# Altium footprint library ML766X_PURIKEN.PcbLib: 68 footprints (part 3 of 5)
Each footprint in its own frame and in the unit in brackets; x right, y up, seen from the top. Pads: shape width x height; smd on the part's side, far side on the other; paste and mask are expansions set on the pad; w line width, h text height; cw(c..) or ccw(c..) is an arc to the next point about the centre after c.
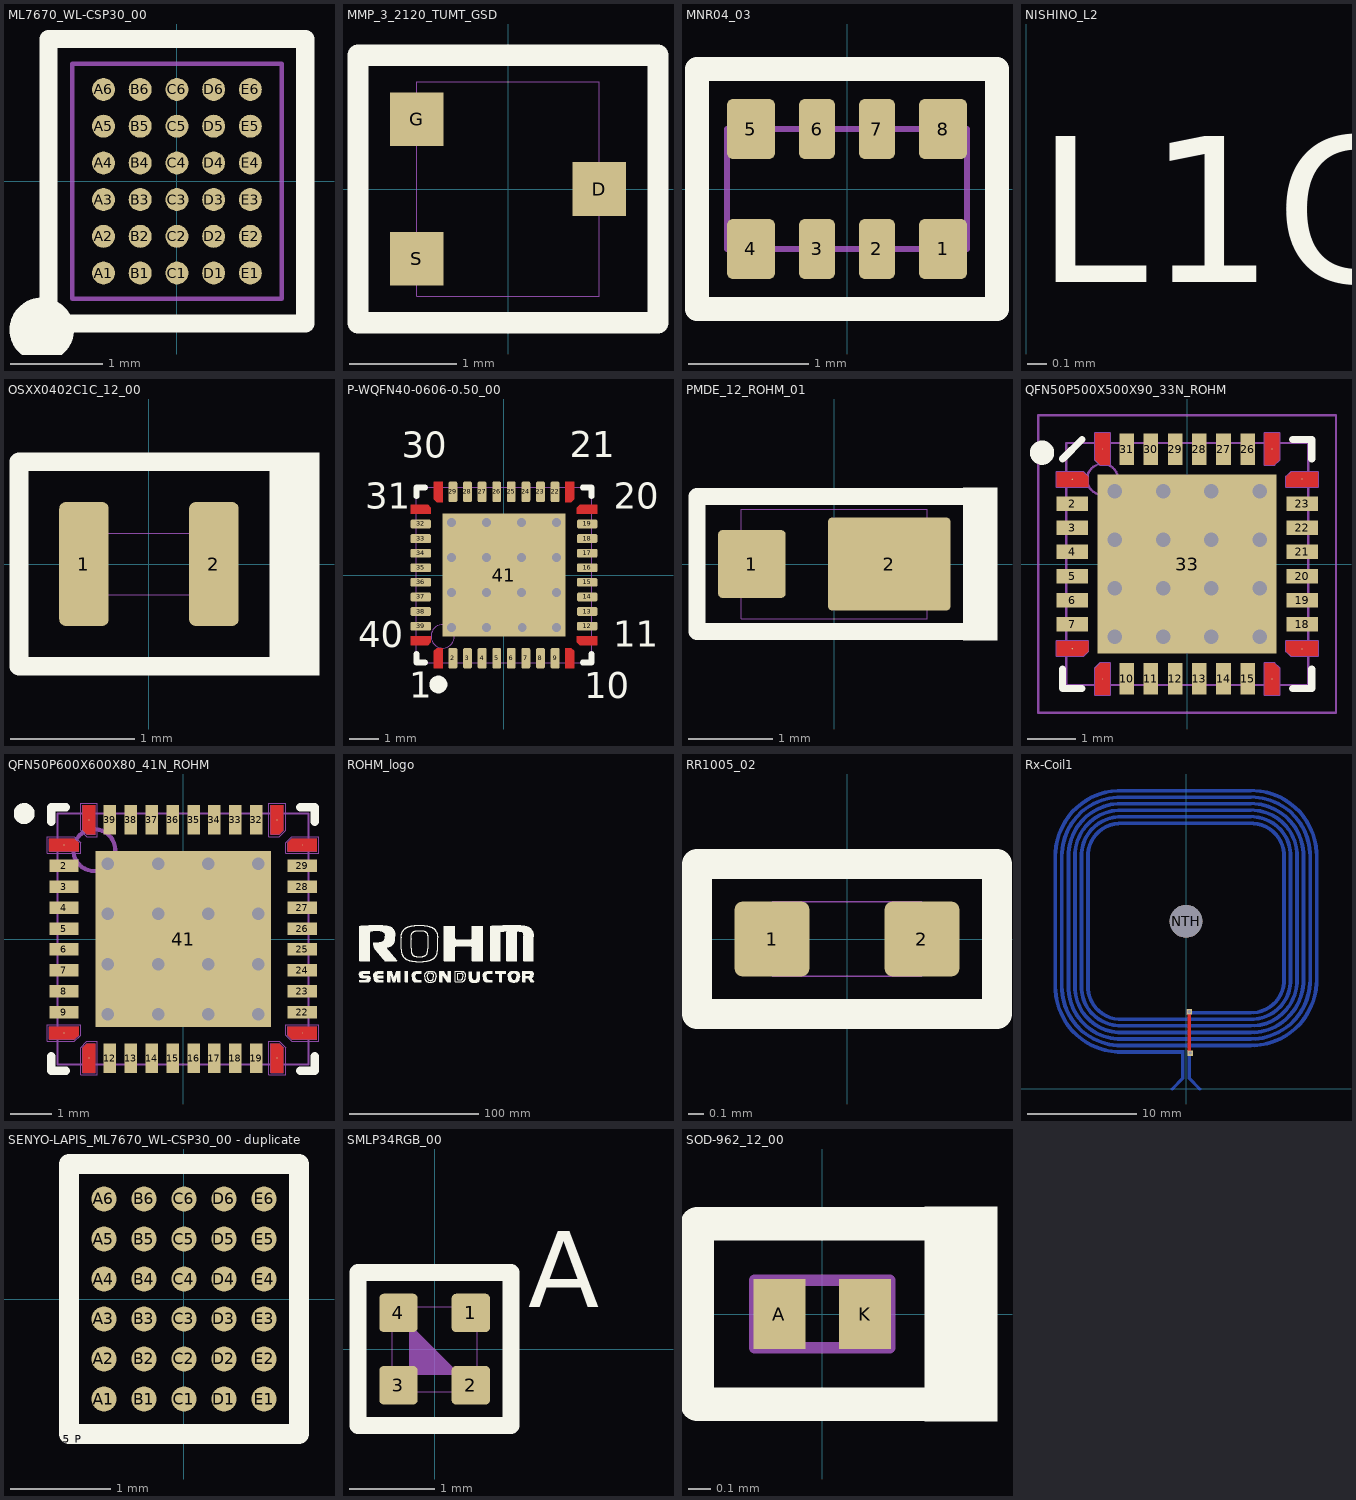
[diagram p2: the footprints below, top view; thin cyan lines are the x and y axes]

## ML7670_WL-CSP30_00 [mm]
height 0.48
pads (30):
  round 0.25 smd paste-2539.97 mask+0.013: A1(-0.8,-1) A2(-0.8,-0.6) A3(-0.8,-0.2) A4(-0.8,0.2) A5(-0.8,0.6) A6(-0.8,1) B1(-0.4,-1) B2(-0.4,-0.6) B3(-0.4,-0.2) B4(-0.4,0.2) B5(-0.4,0.6) B6(-0.4,1) C1(0,-1) C2(0,-0.6) C3(0,-0.2) C4(0,0.2) C5(0,0.6) C6(0,1) D1(0.4,-1) D2(0.4,-0.6) D3(0.4,-0.2) D4(0.4,0.2) D5(0.4,0.6) D6(0.4,1) E1(0.8,-1) E2(0.8,-0.6) E3(0.8,-0.2) E4(0.8,0.2) E5(0.8,0.6) E6(0.8,1)
Top Overlay:
  circle w0.5: c-1.473,-1.619 r0.1
  lines w0.2: -1.4,-1.55 0.2,-1.55 1.4,-1.55 1.4,1.55 -1.4,1.55 -1.4,-1.55
Top Component Outline:
  lines w0.05: -1.14,-1.28 -1.14,1.28 1.14,1.28 1.14,-1.28 -1.14,-1.28
3D body: height 0.4, standoff 0, extent -1.14,-1.28 1.14,1.28
3D body: height 0.41, standoff 0.4, extent -0.993,-1.212 -0.593,-0.812

## MMP_3_2120_TUMT_GSD [mm] "default"
height 0.9
pads (3):
  rect 0.5x0.5 smd paste+0 mask+0.05: D(0.85,0) G(-0.85,0.65) S(-0.85,-0.65)
Top Overlay:
  lines w0.2: -1.4,-1.25 1.4,-1.25 1.4,1 1.4,1.25 -1.4,1.25 -1.4,0.3 -1.4,-1.25
Top Component Outline:
  lines w0.01: -1.05,-0.8 -0.65,-0.8 -0.65,-0.5 -1.05,-0.5 -1.05,-0.8 ; -1.05,0.5 -0.65,0.5 -0.65,0.8 -1.05,0.8 -1.05,0.5 ; -0.85,-1 0.85,-1 0.85,1 -0.85,1 -0.85,-1 ; 0.65,-0.15 0.65,0.15 1.05,0.15 1.05,-0.15 0.65,-0.15
3D body "sot-323t_TUMT3.STEP": height 0.85, standoff 0, extent -1.05,-1 1.05,1

## MNR04_03 [mm]
height 0.35
pads (8):
  rrect25% 0.4x0.5 smd paste-2539.97 mask+0.025: 1(0.8,-0.5) 4(-0.8,-0.5) 5(-0.8,0.5) 8(0.8,0.5)
  rrect33% 0.3x0.5 smd paste-2539.97 mask+0.025: 2(0.25,-0.5) 3(-0.25,-0.5) 6(-0.25,0.5) 7(0.25,0.5)
Top Overlay:
  lines w0.2: -1.25,-1 0,-1 1.25,-1 1.25,1 -1.25,1 -1.25,-1
Top Component Outline:
  lines w0.05: -1,-0.5 -1,0.5 1,0.5 1,-0.5 -1,-0.5
3D body "MNR04.step": height 0.35, standoff 0, extent -1,-0.5 1,0.5

## NISHINO_L2 [mm]
Top Layer:
  text "L1PT" at 0,-1.15 h1.52
Bottom Layer:
  text "L2PT" at 2.831,-1.2 h1.52
Top Overlay:
  text "L1CM" at 0.05,-4.417 h1.52
Bottom Overlay:
  text "L2CM" at 3.433,-4.367 h1.52
MASK:
  text "L1METAL" at 0.1,-6 h1.52
MASK_B:
  text "L2METAL" at 5.815,-6.05 h1.52
Top Solder:
  text "L1SR" at 0.05,-2.867 h1.52
Bottom Solder:
  text "L2SR" at 3.04,-2.867 h1.52

## OSXX0402C1C_12_00 [mm]
height 0.4
pads (2):
  rrect25% 0.4x1 smd: 1(-0.525,0) 2(0.525,0)
Top Overlay:
  region: 0.975,0.9 1.375,0.9 1.375,-0.9 0.975,-0.9
  lines w0.15: 1.3,-0.825 -1.05,-0.825 -1.05,0.825 1.3,0.825
Top Component Outline:
  lines w0.01: -0.5,-0.25 0.5,-0.25 0.5,0.25 -0.5,0.25 -0.5,-0.25
3D body: height 0.4, standoff 0, extent -0.5,-0.25 0.5,0.25

## P-WQFN40-0606-0.50_00 [mm]
height 0.8
pads (57):
  round 0.005 smd: 1(-2.25,-2.85) 10(2.25,-2.85) 11(2.85,-2.25) 20(2.85,2.25) 21(2.25,2.85) 30(-2.25,2.85) 31(-2.85,2.25) 40(-2.85,-2.25)
  rrect33% 0.3x0.7 smd paste-2539.97 mask+0.025: 2(-1.75,-2.85) 3(-1.25,-2.85) 4(-0.75,-2.85) 5(-0.25,-2.85) 6(0.25,-2.85) 7(0.75,-2.85) 8(1.25,-2.85) 9(1.75,-2.85) 22(1.75,2.85) 23(1.25,2.85) 24(0.75,2.85) 25(0.25,2.85) 26(-0.25,2.85) 27(-0.75,2.85) 28(-1.25,2.85) 29(-1.75,2.85)
  rrect33% 0.7x0.3 smd paste-2539.97 mask+0.025: 12(2.85,-1.75) 13(2.85,-1.25) 14(2.85,-0.75) 15(2.85,-0.25) 16(2.85,0.25) 17(2.85,0.75) 18(2.85,1.25) 19(2.85,1.75) 32(-2.85,1.75) 33(-2.85,1.25) 34(-2.85,0.75) 35(-2.85,0.25) 36(-2.85,-0.25) 37(-2.85,-0.75) 38(-2.85,-1.25) 39(-2.85,-1.75)
  rect 4.2x4.2 smd mask+0.051: 41(0,0)
  round 0.6 / inner round 1.524 / far side round 0.6 hole 0.3 mask-0.051: VIA0.3_0.6_0.6_00(-1.8,-1.8) VIA0.3_0.6_0.6_00(-1.8,-0.6) VIA0.3_0.6_0.6_00(-1.8,0.6) VIA0.3_0.6_0.6_00(-1.8,1.8) VIA0.3_0.6_0.6_00(-0.6,-1.8) VIA0.3_0.6_0.6_00(-0.6,-0.6) VIA0.3_0.6_0.6_00(-0.6,0.6) VIA0.3_0.6_0.6_00(-0.6,1.8) VIA0.3_0.6_0.6_00(0.6,-0.6) VIA0.3_0.6_0.6_00(0.6,0.6) VIA0.3_0.6_0.6_00(0.6,1.8) VIA0.3_0.6_0.6_00(0.625,-1.8) VIA0.3_0.6_0.6_00(1.8,-1.8) VIA0.3_0.6_0.6_00(1.8,-0.6) VIA0.3_0.6_0.6_00(1.8,0.6) VIA0.3_0.6_0.6_00(1.8,1.8)
Top Layer:
  region: -2.5,-2.1 -2.5,-2.3 -2.6,-2.4 -3.2,-2.4 -3.2,-2.1
  region: -2.5,2.3 -2.5,2.1 -3.2,2.1 -3.2,2.4 -2.6,2.4
  region: -2.1,2.5 -2.3,2.5 -2.4,2.6 -2.4,3.2 -2.1,3.2
  region: 2.3,2.5 2.1,2.5 2.1,3.2 2.4,3.2 2.4,2.6
  region: 2.5,2.1 2.5,2.3 2.6,2.4 3.2,2.4 3.2,2.1
  region: 2.5,-2.3 2.5,-2.1 3.2,-2.1 3.2,-2.4 2.6,-2.4
  region: 2.1,-2.5 2.3,-2.5 2.4,-2.6 2.4,-3.2 2.1,-3.2
  region: -2.3,-2.5 -2.1,-2.5 -2.1,-3.2 -2.4,-3.2 -2.4,-2.6
Top Overlay:
  region: -1.95,-3.75 -1.95,-3.69 -1.996,-3.58 -2.08,-3.496 -2.19,-3.45 -2.31,-3.45 -2.42,-3.496 -2.504,-3.58 -2.55,-3.69 -2.55,-3.81 -2.504,-3.92 -2.42,-4.004 -2.31,-4.05 -2.25,-4.05 -2.19,-4.05 -2.08,-4.004 -1.996,-3.92 -1.95,-3.81 -1.95,-3.69 -1.996,-3.58 -2.08,-3.496 -2.19,-3.45 -2.31,-3.45 -2.42,-3.496 -2.504,-3.58 -2.55,-3.69 -2.55,-3.75 -2.55,-3.81 -2.504,-3.92 -2.42,-4.004 -2.31,-4.05 -2.19,-4.05 -2.08,-4.004 -1.996,-3.92 -1.95,-3.81 -1.95,-3.69 -1.996,-3.58 -2.08,-3.496 -2.19,-3.45 -2.25,-3.45 -2.31,-3.45 -2.42,-3.496 -2.504,-3.58 -2.55,-3.69 -2.55,-3.81 -2.504,-3.92 -2.42,-4.004 -2.31,-4.05 -2.19,-4.05 -2.08,-4.004 -1.996,-3.92 -1.95,-3.81
  lines w0.2: -3,-2.7 -3,-3 -2.7,-3 ; -3,2.7 -3,3 -2.7,3 ; 2.7,-3 3,-3 3,-2.7 ; 2.7,3 3,3 3,2.7
  text "40" at -5,-2.767 h1.52
  text "1" at -3.25,-4.5 h1.52
  text "10" at 2.75,-4.517 h1.52
  text "11" at 3.75,-2.75 h1.52
  text "20" at 3.751,1.983 h1.52
  text "21" at 2.251,3.75 h1.52
  text "30" at -3.5,3.733 h1.52
  text "31" at -4.75,1.983 h1.52
MASK:
  dashed: -2.5,-2.1 -2.5,-2.3 -2.6,-2.4 -3.2,-2.4 -3.2,-2.1
  dashed: -2.5,2.3 -2.5,2.1 -3.2,2.1 -3.2,2.4 -2.6,2.4
  dashed: -2.1,2.5 -2.3,2.5 -2.4,2.6 -2.4,3.2 -2.1,3.2
  dashed: 2.3,2.5 2.1,2.5 2.1,3.2 2.4,3.2 2.4,2.6
  dashed: 2.5,2.1 2.5,2.3 2.6,2.4 3.2,2.4 3.2,2.1
  dashed: 2.5,-2.3 2.5,-2.1 3.2,-2.1 3.2,-2.4 2.6,-2.4
  dashed: 2.1,-2.5 2.3,-2.5 2.4,-2.6 2.4,-3.2 2.1,-3.2
  dashed: -2.3,-2.5 -2.1,-2.5 -2.1,-3.2 -2.4,-3.2 -2.4,-2.6
  region: -2.1,-2.1 -2.1,-0.15 -0.15,-0.15 -0.15,-2.1
  region: -2.1,0.15 -2.1,2.1 -0.15,2.1 -0.15,0.15
  region: 0.15,-2.1 0.15,-0.15 2.1,-0.15 2.1,-2.1
  region: 0.15,0.15 0.15,2.1 2.1,2.1 2.1,0.15
Top Solder:
  dashed: -3.25,-2.05 -2.45,-2.05 -2.45,-2.321 -2.579,-2.45 -3.25,-2.45
  dashed: -3.25,2.45 -2.579,2.45 -2.45,2.321 -2.45,2.05 -3.25,2.05
  dashed: -2.05,3.25 -2.05,2.45 -2.321,2.45 -2.45,2.579 -2.45,3.25
  dashed: 2.45,3.25 2.45,2.579 2.321,2.45 2.05,2.45 2.05,3.25
  dashed: 3.25,2.05 2.45,2.05 2.45,2.321 2.579,2.45 3.25,2.45
  dashed: 3.25,-2.45 2.579,-2.45 2.45,-2.321 2.45,-2.05 3.25,-2.05
  dashed: 2.05,-3.25 2.05,-2.45 2.321,-2.45 2.45,-2.579 2.45,-3.25
  dashed: -2.45,-3.25 -2.45,-2.579 -2.321,-2.45 -2.05,-2.45 -2.05,-3.25
Top Component Outline:
  circle w0.01: c-2.1,-2.1 r0.4
  lines w0.01: -3,-3 3,-3 3,3 -3,3 -3,-3
3D body: height 0.8, standoff 0, extent -3,-3 3,3

## PCBComponent_1 [mm]

## PMDE_12_ROHM_01 [mm]
height 0.95
pads (2):
  rrect12% 0.8x0.8 smd: 1(-0.975,0)
  rrect9% 1.45x1.1 smd: 2(0.65,0)
Top Overlay:
  region: 1.525,0.9 1.925,0.9 1.925,-0.9 1.525,-0.9
  lines w0.2: 1.625,-0.8 -1.625,-0.8 -1.625,0.8 1.625,0.8
Top Component Outline:
  lines w0.01: -1.1,-0.65 1.1,-0.65 1.1,0.65 -1.1,0.65 -1.1,-0.65
3D body: height 0.95, standoff 0, extent -1.1,-0.65 1.1,0.65

## QFN50P500X500X90_33N_ROHM [mm] "QFN, 32-Leads, Body 5.00x5.00mm, Pitch 0.50mm, Thermal Pad 3.90x3.90mm"
height 0.9
pads (33):
  round 0.025 smd mask+0.05: 1(-2.375,1.75) 8(-2.375,-1.75) 9(-1.75,-2.375) 16(1.75,-2.375) 17(2.375,-1.75) 24(2.375,1.75) 25(1.75,2.375) 32(-1.75,2.375)
  rect 0.65x0.3 smd mask+0.05: 2(-2.375,1.25) 3(-2.375,0.75) 4(-2.375,0.25) 5(-2.375,-0.25) 6(-2.375,-0.75) 7(-2.375,-1.25) 18(2.375,-1.25) 19(2.375,-0.75) 20(2.375,-0.25) 21(2.375,0.25) 22(2.375,0.75) 23(2.375,1.25)
  rect 0.3x0.65 smd mask+0.05: 10(-1.25,-2.375) 11(-0.75,-2.375) 12(-0.25,-2.375) 13(0.25,-2.375) 14(0.75,-2.375) 15(1.25,-2.375) 26(1.25,2.375) 27(0.75,2.375) 28(0.25,2.375) 29(-0.25,2.375) 30(-0.75,2.375) 31(-1.25,2.375)
  rect 3.7x3.7 smd mask+0.05: 33(0,0)
via 1.5,1.5 diameter 0.6 hole 0.3
via 0.5,1.5 diameter 0.6 hole 0.3
via -0.5,1.5 diameter 0.6 hole 0.3
via -1.5,1.5 diameter 0.6 hole 0.3
via 1.5,0.5 diameter 0.6 hole 0.3
via 0.5,0.5 diameter 0.6 hole 0.3
via -0.5,0.5 diameter 0.6 hole 0.3
via -1.5,0.5 diameter 0.6 hole 0.3
via 1.5,-0.5 diameter 0.6 hole 0.3
via 0.5,-0.5 diameter 0.6 hole 0.3
via -0.5,-0.5 diameter 0.6 hole 0.3
via -1.5,-0.5 diameter 0.6 hole 0.3
via 1.5,-1.5 diameter 0.6 hole 0.3
via 0.5,-1.5 diameter 0.6 hole 0.3
via -0.5,-1.5 diameter 0.6 hole 0.3
via -1.5,-1.5 diameter 0.6 hole 0.3
Top Layer:
  region: -1.9,2.15 -1.8,2.05 -1.6,2.05 -1.6,2.7 -1.9,2.7
  region: -2.05,1.8 -2.15,1.9 -2.7,1.9 -2.7,1.6 -2.05,1.6
  region: 2.15,1.9 2.05,1.8 2.05,1.6 2.7,1.6 2.7,1.9
  region: 1.8,2.05 1.9,2.15 1.9,2.7 1.6,2.7 1.6,2.05
  region: 1.9,-2.15 1.8,-2.05 1.6,-2.05 1.6,-2.7 1.9,-2.7
  region: 2.05,-1.8 2.15,-1.9 2.7,-1.9 2.7,-1.6 2.05,-1.6
  region: -2.15,-1.9 -2.05,-1.8 -2.05,-1.6 -2.7,-1.6 -2.7,-1.9
  region: -1.8,-2.05 -1.9,-2.15 -1.9,-2.7 -1.6,-2.7 -1.6,-2.05
Top Overlay:
  circle w0.25: c-3,2.3 r0.125
  lines w0.15: -2.575,-2.175 -2.575,-2.575 -2.175,-2.575 ; -2.575,2.175 -2.175,2.575 ; 2.175,-2.575 2.575,-2.575 2.575,-2.175 ; 2.175,2.575 2.575,2.575 2.575,2.175
Top Solder:
  region: -1.825,2 -1.95,2.125 -1.95,2.75 -1.55,2.75 -1.55,2
  region: -2,1.55 -2.75,1.55 -2.75,1.95 -2.125,1.95 -2,1.825
  region: 2,1.825 2.125,1.95 2.75,1.95 2.75,1.55 2,1.55
  region: 1.55,2 1.55,2.75 1.95,2.75 1.95,2.125 1.825,2
  region: 1.825,-2 1.95,-2.125 1.95,-2.75 1.55,-2.75 1.55,-2
  region: 2,-1.55 2.75,-1.55 2.75,-1.95 2.125,-1.95 2,-1.825
  region: -2,-1.825 -2.125,-1.95 -2.75,-1.95 -2.75,-1.55 -2,-1.55
  region: -1.55,-2 -1.55,-2.75 -1.95,-2.75 -1.95,-2.125 -1.825,-2
Top Component Outline:
  circle w0.05: c-1.75,1.75 r0.32
  lines w0.05: -2.7,-1.9 -2.7,-1.6 -2.05,-1.6 -2.05,-1.8 -2.15,-1.9 -2.7,-1.9 ; -2.7,1.6 -2.05,1.6 -2.05,1.8 -2.15,1.9 -2.7,1.9 -2.7,1.6 ; -2.5,-2.5 -2.5,2.5 2.5,2.5 2.5,-2.5 -2.5,-2.5 ; -1.9,-2.7 -1.9,-2.15 -1.8,-2.05 -1.6,-2.05 -1.6,-2.7 -1.9,-2.7 ; -1.9,2.15 -1.9,2.7 -1.6,2.7 -1.6,2.05 -1.8,2.05 -1.9,2.15 ; 1.6,-2.7 1.9,-2.7 1.9,-2.15 1.8,-2.05 1.6,-2.05 1.6,-2.7 ; 1.6,2.05 1.8,2.05 1.9,2.15 1.9,2.7 1.6,2.7 1.6,2.05 ; 2.05,-1.8 2.15,-1.9 2.7,-1.9 2.7,-1.6 2.05,-1.6 2.05,-1.8 ; 2.05,1.6 2.05,1.8 2.15,1.9 2.7,1.9 2.7,1.6 2.05,1.6
  lines w0.1: -0.5,0 0.5,0 ; 0,-0.5 0,0.5
Mechanical 15:
  lines w0.05: -3.075,-3.075 -3.075,3.075 3.075,3.075 3.075,-3.075 -3.075,-3.075
3D body "QFN50P500X500X90_HS-33N.step": height 0.9, standoff 0, extent -2.501,-2.501 2.501,2.501

## QFN50P600X600X80_41N_ROHM [mm] "QFN, 40-Leads, Body 6.00x6.00mm, Pitch 0.50mm, Thermal Pad 4.20x4.20mm"
height 0.8
pads (41):
  round 0.025 smd mask+0: 1(-2.85,2.25) 10(-2.85,-2.25) 11(-2.25,-2.85) 20(2.25,-2.85) 21(2.85,-2.25) 30(2.85,2.25) 31(2.25,2.85) 40(-2.25,2.85)
  rect 0.7x0.3 smd mask+0.05: 2(-2.85,1.75) 3(-2.85,1.25) 4(-2.85,0.75) 5(-2.85,0.25) 6(-2.85,-0.25) 7(-2.85,-0.75) 8(-2.85,-1.25) 9(-2.85,-1.75) 22(2.85,-1.75) 23(2.85,-1.25) 24(2.85,-0.75) 25(2.85,-0.25) 26(2.85,0.25) 27(2.85,0.75) 28(2.85,1.25) 29(2.85,1.75)
  rect 0.3x0.7 smd mask+0.05: 12(-1.75,-2.85) 13(-1.25,-2.85) 14(-0.75,-2.85) 15(-0.25,-2.85) 16(0.25,-2.85) 17(0.75,-2.85) 18(1.25,-2.85) 19(1.75,-2.85) 32(1.75,2.85) 33(1.25,2.85) 34(0.75,2.85) 35(0.25,2.85) 36(-0.25,2.85) 37(-0.75,2.85) 38(-1.25,2.85) 39(-1.75,2.85)
  rect 4.2x4.2 smd mask+0.05: 41(0,0)
via 1.8,-1.8 diameter 0.6 hole 0.3
via 1.8,-0.6 diameter 0.6 hole 0.3
via 1.8,0.6 diameter 0.6 hole 0.3
via 1.8,1.8 diameter 0.6 hole 0.3
via 0.6,-1.8 diameter 0.6 hole 0.3
via 0.6,-0.6 diameter 0.6 hole 0.3
via 0.6,0.6 diameter 0.6 hole 0.3
via 0.6,1.8 diameter 0.6 hole 0.3
via -0.6,-1.8 diameter 0.6 hole 0.3
via -0.6,-0.6 diameter 0.6 hole 0.3
via -0.6,0.6 diameter 0.6 hole 0.3
via -0.6,1.8 diameter 0.6 hole 0.3
via -1.8,-1.8 diameter 0.6 hole 0.3
via -1.8,-0.6 diameter 0.6 hole 0.3
via -1.8,0.6 diameter 0.6 hole 0.3
via -1.8,1.8 diameter 0.6 hole 0.3
Top Layer:
  region: -2.5,-2.3 -2.6,-2.4 -3.2,-2.4 -3.2,-2.1 -2.5,-2.1
  region: -2.5,2.3 -2.6,2.4 -3.2,2.4 -3.2,2.1 -2.5,2.1
  region: -2.3,2.5 -2.4,2.6 -2.4,3.2 -2.1,3.2 -2.1,2.5
  region: 2.3,2.5 2.4,2.6 2.4,3.2 2.1,3.2 2.1,2.5
  region: 2.5,2.3 2.6,2.4 3.2,2.4 3.2,2.1 2.5,2.1
  region: 2.5,-2.3 2.6,-2.4 3.2,-2.4 3.2,-2.1 2.5,-2.1
  region: 2.3,-2.5 2.4,-2.6 2.4,-3.2 2.1,-3.2 2.1,-2.5
  region: -2.3,-2.5 -2.4,-2.6 -2.4,-3.2 -2.1,-3.2 -2.1,-2.5
Top Overlay:
  circle w0.25: c-3.8,3 r0.125
  lines w0.2: -3.15,-2.8 -3.15,-3.15 -2.8,-3.15 ; -3.15,2.8 -3.15,3.15 -2.8,3.15 ; 2.8,-3.15 3.15,-3.15 3.15,-2.8 ; 2.8,3.15 3.15,3.15 3.15,2.8
Top Solder:
  region: -3.25,-2.05 -2.45,-2.05 -2.45,-2.3 -2.6,-2.45 -3.25,-2.45
  region: -3.25,2.45 -3.25,2.05 -2.45,2.05 -2.45,2.3 -2.6,2.45
  region: -2.05,3.25 -2.05,2.45 -2.3,2.45 -2.45,2.6 -2.45,3.25
  region: 2.45,3.25 2.05,3.25 2.05,2.45 2.3,2.45 2.45,2.6
  region: 3.25,2.05 2.45,2.05 2.45,2.3 2.6,2.45 3.25,2.45
  region: 3.25,-2.45 3.25,-2.05 2.45,-2.05 2.45,-2.3 2.6,-2.45
  region: 2.05,-3.25 2.05,-2.45 2.3,-2.45 2.45,-2.6 2.45,-3.25
  region: -2.45,-3.25 -2.05,-3.25 -2.05,-2.45 -2.3,-2.45 -2.45,-2.6
Top Component Outline:
  circle w0.1: c-2.125,2.125 r0.5
  lines w0.005: -3.25,-2.45 -3.25,-2.05 -2.55,-2.05 -2.45,-2.05 -2.45,-2.3 -2.6,-2.45 -3.25,-2.45 ; -3.25,2.05 -2.55,2.05 -2.45,2.05 -2.45,2.3 -2.6,2.45 -3.25,2.45 -3.25,2.05 ; -3.2,-2.4 -2.6,-2.4 -2.5,-2.3 -2.5,-2.1 -3.2,-2.1 -3.2,-2.4 ; -3.2,2.1 -2.5,2.1 -2.5,2.3 -2.6,2.4 -3.2,2.4 -3.2,2.1 ; -2.45,-3.25 -2.05,-3.25 -2.05,-2.55 -2.05,-2.45 -2.3,-2.45 -2.45,-2.6 -2.45,-3.25 ; -2.45,2.6 -2.45,3.25 -2.05,3.25 -2.05,2.55 -2.05,2.45 -2.3,2.45 -2.45,2.6 ; -2.4,-3.2 -2.4,-2.6 -2.3,-2.5 -2.1,-2.5 -2.1,-3.2 -2.4,-3.2 ; -2.4,2.6 -2.4,3.2 -2.1,3.2 -2.1,2.5 -2.3,2.5 -2.4,2.6 ; 2.05,-3.25 2.05,-2.55 2.05,-2.45 2.3,-2.45 2.45,-2.6 2.45,-3.25 2.05,-3.25 ; 2.05,2.45 2.3,2.45 2.45,2.6 2.45,3.25 2.05,3.25 2.05,2.55 2.05,2.45 ; 2.1,-3.2 2.1,-2.5 2.3,-2.5 2.4,-2.6 2.4,-3.2 2.1,-3.2 ; 2.1,2.5 2.3,2.5 2.4,2.6 2.4,3.2 2.1,3.2 2.1,2.5 ; 2.45,-2.3 2.6,-2.45 3.25,-2.45 3.25,-2.05 2.55,-2.05 2.45,-2.05 2.45,-2.3 ; 2.45,2.05 2.45,2.3 2.6,2.45 3.25,2.45 3.25,2.05 2.55,2.05 2.45,2.05 ; 2.5,-2.3 2.6,-2.4 3.2,-2.4 3.2,-2.1 2.5,-2.1 2.5,-2.3 ; 2.5,2.1 2.5,2.3 2.6,2.4 3.2,2.4 3.2,2.1 2.5,2.1
  lines w0.05: -3,-3 3,-3 3,3 -3,3 -3,-3
3D body "QFN50P600X600X80_HS-41N.step": height 0.8, standoff 0, extent -3.001,-3.001 3.001,3.001

## ROHM_logo [mm]
Top Overlay:
  drawing of 19524 lines, arcs and shapes, not listed

## RR1005_02 [mm]
pads (2):
  rrect22% 0.5x0.5 smd: 1(-0.5,0) 2(0.5,0)
Top Overlay:
  lines w0.2: -1,-0.5 1,-0.5 1,0.5 -1,0.5 -1,-0.5
Top Component Outline:
  lines w0.01: -0.5,-0.25 0.5,-0.25 0.5,0.25 -0.5,0.25 -0.5,-0.25
3D body "RESC1005X35N.step": height 0.35, standoff 0, extent -0.5,-0.25 0.5,0.25

## Rx-Coil1 [mm]
pads (3):
  rect 0.5x0.5 hole 0.3: 1(0.4,3.3) 2(0.3,7.1)
  round 3 hole 3 unplated mask+0.25: NTH(0,15.4)
Top Layer:
  lines w0.3: 0.3,3.4 0.3,5.45 0.3,7.1
Bottom Layer:
  region: 742 vertices and 0 holes, not listed, extent -12.15,2.4 12.15,27.55
  region: 0.45,2.4 0.45,3.55 0.15,3.55 0.15,2.4
  lines w0.3: -1.27,0 -0.3,0.97 -0.3,2.5 ; 0.3,2.5 0.3,0.97 1.27,0

## SENYO-LAPIS_ML7670_WL-CSP30_00 - duplicate [mm]
height 0.48
pads (31):
  round 0.25 smd paste-2539.97 mask+0.013: A1(-0.8,-1) A2(-0.8,-0.6) A3(-0.8,-0.2) A4(-0.8,0.2) A5(-0.8,0.6) A6(-0.8,1) B1(-0.4,-1) B2(-0.4,-0.6) B3(-0.4,-0.2) B4(-0.4,0.2) B5(-0.4,0.6) B6(-0.4,1) C1(0,-1) C2(0,-0.6) C3(0,-0.2) C4(0,0.2) C5(0,0.6) C6(0,1) D1(0.4,-1) D2(0.4,-0.6) D3(0.4,-0.2) D4(0.4,0.2) D5(0.4,0.6) D6(0.4,1) E1(0.8,-1) E2(0.8,-0.6) E3(0.8,-0.2) E4(0.8,0.2) E5(0.8,0.6) E6(0.8,1)
  round 0.5 on Top Overlay: C0.5_P(-1.2,-1.4)
Top Overlay:
  lines w0.2: -1.15,-1.35 -1.15,1.35 1.15,1.35 1.15,-1.35 0,-1.35 -1.15,-1.35
3D body: height 0.48, standoff 0, extent -1.14,-1.28 1.14,1.28

## SMLP34RGB_00 [mm]
height 0.2
pads (4):
  rrect22% 0.45x0.45 smd: 1(0.425,0.425) 2(0.425,-0.425) 3(-0.425,-0.425) 4(-0.425,0.425)
Top Overlay:
  lines w0.2: -0.9,-0.9 -0.9,0.9 0.9,0.9 0.9,-0.9 0,-0.9 -0.9,-0.9
  text "A" at 1.1,0.2 h1.52
Top Component Outline:
  region: -0.3,0.3 0.3,-0.3 -0.3,-0.3
  lines w0.01: -0.5,-0.5 -0.5,0.5 0.5,0.5 0.5,-0.5 -0.5,-0.5
3D body: height 0.2, standoff 0, extent -0.5,-0.5 0.5,0.5

## SOD-962_12_00 [mm]
height 0.29
pads (2):
  rect 0.23x0.31 smd paste+0 mask+0: A(-0.19,0) K(0.19,0)
Top Overlay:
  region: 0.455,0.475 0.775,0.475 0.775,-0.475 0.455,-0.475
  lines w0.15: 0.545,-0.4 -0.555,-0.4 -0.555,0.4 0.545,0.4
Top Solder:
  region: -0.355,-0.205 -0.355,0.205 -0.075,0.205 -0.075,-0.205
  region: 0.075,-0.205 0.075,0.205 0.355,0.205 0.355,-0.205
Top Component Outline:
  lines w0.05: -0.3,-0.15 -0.3,0.15 0.3,0.15 0.3,-0.15 -0.3,-0.15
3D body "SOD962.step": height 0.29, standoff 0, extent -0.3,-0.147 0.3,0.147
